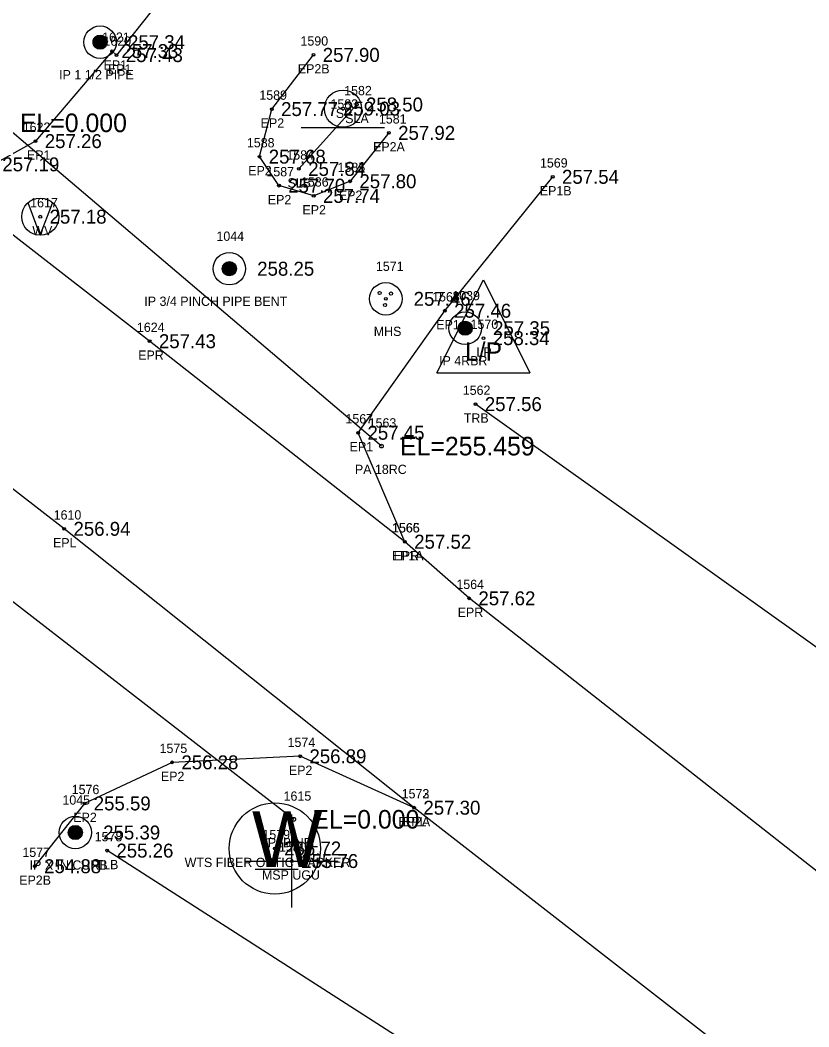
# Model space of a CAD drawing. Extents: x 1961231 to 1962574, y 799865 to 801120.
# Drawn here: x 1961462.6 to 1961547.5, y 800894.4 to 801002.7 of the extents above; entities that cross this region are included whole.
import ezdxf

# ---------------------------------------------------------------- set-up
doc = ezdxf.new("R2010")
doc.units = 0
for name, color, linetype in [('RD_EX_BldgApp', 7, 'Continuous'), ('RD_EX_BldgApp_txCode', 7, 'Continuous'), ('RD_EX_DR_Inlet', 7, 'Continuous'), ('RD_EX_DR_Pipe', 7, 'Continuous'), ('RD_EX_DR_Pipe_txCode', 7, 'Continuous'), ('RD_EX_DV_Prop_txCode', 7, 'Continuous'), ('RD_EX_DV_PropPin', 7, 'Continuous'), ('RD_EX_Misc', 7, 'Continuous'), ('RD_EX_Misc_txCode', 7, 'Continuous'), ('RD_EX_Road', 7, 'Continuous'), ('RD_EX_Road_txCode', 7, 'Continuous'), ('RD_EX_TX_BldgApp_ELEV', 7, 'Continuous'), ('RD_EX_TX_DV_Prop_ELEV', 7, 'Continuous'), ('RD_EX_TX_Misc_ELEV', 7, 'Continuous'), ('RD_EX_TX_Road_ELEV', 7, 'Continuous'), ('RD_EX_TX_UT_ELEV', 7, 'Continuous'), ('RD_EX_TX_VEG_ELEV', 7, 'Continuous'), ('RD_EX_UT', 7, 'Continuous'), ('RD_EX_UT_txCode', 7, 'Continuous'), ('RD_EX_VEG', 7, 'Continuous'), ('RD_EX_VEG_txCode', 7, 'Continuous'), ('RD_SMD_Locator', 7, 'Continuous'), ('RD_TX_Pipe_ElevEX', 7, 'Continuous')]:
    doc.layers.add(name, color=color, linetype=linetype)

msp = doc.modelspace()

# ---------------------------------------------------------------- linework, layer by layer
at = {"layer": 'RD_EX_BldgApp'}
msp.add_line((1961492.83, 800991.17), (1961501.83, 800991.17), dxfattribs=at)
msp.add_circle((1961497.35, 800993.19), 2, dxfattribs=at)
at = {"layer": 'RD_EX_DR_Inlet'}
for centre, radius in [((1961501.95, 800972.72), 1.75), ((1961501.29, 800973.35), 0.175), ((1961502.51, 800973.28), 0.175), ((1961501.87, 800972.06), 0.175)]:
    msp.add_circle(centre, radius, dxfattribs=at)
at = {"layer": 'RD_EX_DR_Pipe'}
for p, q in [((1961501.48, 800956.87), (1961460.56, 800991.66)), ((1961427.94, 800966.34), (1961492.04, 800916.71))]:
    msp.add_line(p, q, dxfattribs=at)
at = {"layer": 'RD_EX_DV_PropPin'}
for p, q in [((1961470.46, 801000.15), (1961470.46, 801000.54)), ((1961470.5, 801000.05), (1961470.5, 801000.64)), ((1961470.53, 800999.97), (1961470.53, 801000.71)), ((1961470.57, 800999.92), (1961470.57, 801000.77)), ((1961470.6, 800999.87), (1961470.6, 801000.82)), ((1961470.64, 800999.83), (1961470.64, 801000.86)), ((1961470.67, 800999.79), (1961470.67, 801000.89)), ((1961470.71, 800999.76), (1961470.71, 801000.93)), ((1961470.74, 800999.73), (1961470.74, 801000.95)), ((1961470.78, 800999.71), (1961470.78, 801000.98)), ((1961470.81, 800999.69), (1961470.81, 801001)), ((1961470.85, 800999.67), (1961470.85, 801001.02)), ((1961470.88, 800999.65), (1961470.88, 801001.04)), ((1961470.92, 800999.64), (1961470.92, 801001.05)), ((1961470.95, 800999.62), (1961470.95, 801001.06)), ((1961470.99, 800999.61), (1961470.99, 801001.07)), ((1961471.02, 800999.6), (1961471.02, 801001.08)), ((1961471.06, 800999.6), (1961471.06, 801001.09)), ((1961471.09, 800999.59), (1961471.09, 801001.1)), ((1961471.13, 800999.59), (1961471.13, 801001.1)), ((1961471.16, 800999.58), (1961471.16, 801001.1)), ((1961471.2, 800999.58), (1961471.2, 801001.1)), ((1961471.23, 800999.58), (1961471.23, 801001.1)), ((1961471.27, 800999.59), (1961471.27, 801001.1)), ((1961471.3, 800999.59), (1961471.3, 801001.1)), ((1961471.34, 800999.6), (1961471.34, 801001.09)), ((1961471.37, 800999.6), (1961471.37, 801001.08)), ((1961471.41, 800999.61), (1961471.41, 801001.07)), ((1961471.44, 800999.62), (1961471.44, 801001.06)), ((1961471.48, 800999.64), (1961471.48, 801001.05)), ((1961471.51, 800999.65), (1961471.51, 801001.04)), ((1961471.55, 800999.67), (1961471.55, 801001.02)), ((1961471.58, 800999.69), (1961471.58, 801001)), ((1961471.62, 800999.71), (1961471.62, 801000.98)), ((1961471.65, 800999.73), (1961471.65, 801000.95)), ((1961471.69, 800999.76), (1961471.69, 801000.93)), ((1961471.72, 800999.79), (1961471.72, 801000.89)), ((1961471.76, 800999.83), (1961471.76, 801000.86)), ((1961471.79, 800999.87), (1961471.79, 801000.82)), ((1961471.83, 800999.92), (1961471.83, 801000.77)), ((1961471.86, 800999.97), (1961471.86, 801000.71)), ((1961471.9, 801000.05), (1961471.9, 801000.64)), ((1961471.93, 801000.15), (1961471.93, 801000.54)), ((1961484.44, 800975.59), (1961484.44, 800976.33)), ((1961484.48, 800975.53), (1961484.48, 800976.39)), ((1961484.51, 800975.49), (1961484.51, 800976.43)), ((1961484.55, 800975.45), (1961484.55, 800976.48)), ((1961484.58, 800975.41), (1961484.58, 800976.51)), ((1961484.62, 800975.38), (1961484.62, 800976.54)), ((1961484.65, 800975.35), (1961484.65, 800976.57)), ((1961484.69, 800975.33), (1961484.69, 800976.59)), ((1961484.72, 800975.3), (1961484.72, 800976.62)), ((1961484.76, 800975.28), (1961484.76, 800976.64)), ((1961484.79, 800975.27), (1961484.79, 800976.65)), ((1961484.83, 800975.25), (1961484.83, 800976.67)), ((1961484.86, 800975.24), (1961484.86, 800976.68)), ((1961484.9, 800975.23), (1961484.9, 800976.69)), ((1961484.93, 800975.22), (1961484.93, 800976.7)), ((1961484.97, 800975.21), (1961484.97, 800976.71)), ((1961485, 800975.21), (1961485, 800976.71)), ((1961485.04, 800975.2), (1961485.04, 800976.72)), ((1961485.07, 800975.2), (1961485.07, 800976.72)), ((1961485.11, 800975.2), (1961485.11, 800976.72)), ((1961485.14, 800975.2), (1961485.14, 800976.72)), ((1961485.18, 800975.2), (1961485.18, 800976.72)), ((1961485.21, 800975.21), (1961485.21, 800976.71)), ((1961485.25, 800975.21), (1961485.25, 800976.71)), ((1961485.28, 800975.22), (1961485.28, 800976.7)), ((1961485.32, 800975.23), (1961485.32, 800976.69)), ((1961485.35, 800975.24), (1961485.35, 800976.68)), ((1961485.39, 800975.25), (1961485.39, 800976.67)), ((1961485.42, 800975.27), (1961485.42, 800976.65)), ((1961485.46, 800975.28), (1961485.46, 800976.64)), ((1961485.49, 800975.3), (1961485.49, 800976.62)), ((1961485.53, 800975.33), (1961485.53, 800976.59)), ((1961485.56, 800975.35), (1961485.56, 800976.57)), ((1961485.6, 800975.38), (1961485.6, 800976.54)), ((1961485.63, 800975.41), (1961485.63, 800976.51)), ((1961485.67, 800975.45), (1961485.67, 800976.48)), ((1961485.7, 800975.49), (1961485.7, 800976.43)), ((1961485.74, 800975.53), (1961485.74, 800976.39)), ((1961485.77, 800975.59), (1961485.77, 800976.33)), ((1961484.37, 800975.76), (1961484.37, 800976.16)), ((1961484.41, 800975.66), (1961484.41, 800976.26)), ((1961485.81, 800975.66), (1961485.81, 800976.26)), ((1961485.84, 800975.76), (1961485.84, 800976.16)), ((1961509.8, 800969.26), (1961509.8, 800969.86)), ((1961509.83, 800969.19), (1961509.83, 800969.93)), ((1961509.87, 800969.14), (1961509.87, 800969.99)), ((1961509.9, 800969.09), (1961509.9, 800970.04)), ((1961509.94, 800969.05), (1961509.94, 800970.08)), ((1961509.97, 800969.01), (1961509.97, 800970.11)), ((1961510.01, 800968.98), (1961510.01, 800970.14)), ((1961510.04, 800968.95), (1961510.04, 800970.17)), ((1961510.08, 800968.93), (1961510.08, 800970.2)), ((1961510.11, 800968.91), (1961510.11, 800970.22)), ((1961510.15, 800968.89), (1961510.15, 800970.24)), ((1961510.18, 800968.87), (1961510.18, 800970.25)), ((1961510.22, 800968.85), (1961510.22, 800970.27)), ((1961510.25, 800968.84), (1961510.25, 800970.28)), ((1961510.29, 800968.83), (1961510.29, 800970.29)), ((1961510.32, 800968.82), (1961510.32, 800970.3)), ((1961510.36, 800968.81), (1961510.36, 800970.31)), ((1961510.39, 800968.81), (1961510.39, 800970.32)), ((1961510.43, 800968.8), (1961510.43, 800970.32)), ((1961510.46, 800968.8), (1961510.46, 800970.32)), ((1961510.5, 800968.8), (1961510.5, 800970.32)), ((1961510.53, 800968.8), (1961510.53, 800970.32)), ((1961510.57, 800968.8), (1961510.57, 800970.32)), ((1961510.6, 800968.81), (1961510.6, 800970.32)), ((1961510.64, 800968.81), (1961510.64, 800970.31)), ((1961510.67, 800968.82), (1961510.67, 800970.3)), ((1961510.71, 800968.83), (1961510.71, 800970.29)), ((1961510.74, 800968.84), (1961510.74, 800970.28)), ((1961510.78, 800968.85), (1961510.78, 800970.27)), ((1961510.81, 800968.87), (1961510.81, 800970.25)), ((1961510.85, 800968.89), (1961510.85, 800970.24)), ((1961510.88, 800968.91), (1961510.88, 800970.22)), ((1961510.92, 800968.93), (1961510.92, 800970.2)), ((1961510.95, 800968.95), (1961510.95, 800970.17)), ((1961510.99, 800968.98), (1961510.99, 800970.14)), ((1961511.02, 800969.01), (1961511.02, 800970.11)), ((1961511.06, 800969.05), (1961511.06, 800970.08)), ((1961511.09, 800969.09), (1961511.09, 800970.04)), ((1961511.13, 800969.14), (1961511.13, 800969.99)), ((1961511.16, 800969.19), (1961511.16, 800969.93)), ((1961511.2, 800969.26), (1961511.2, 800969.86)), ((1961509.76, 800969.37), (1961509.76, 800969.76)), ((1961511.23, 800969.37), (1961511.23, 800969.76)), ((1961467.86, 800914.92), (1961467.86, 800915.66)), ((1961467.9, 800914.86), (1961467.9, 800915.71)), ((1961467.93, 800914.81), (1961467.93, 800915.76)), ((1961467.97, 800914.77), (1961467.97, 800915.8)), ((1961468, 800914.74), (1961468, 800915.84)), ((1961468.04, 800914.71), (1961468.04, 800915.87)), ((1961468.07, 800914.68), (1961468.07, 800915.9)), ((1961468.11, 800914.65), (1961468.11, 800915.92)), ((1961468.14, 800914.63), (1961468.14, 800915.94)), ((1961468.18, 800914.61), (1961468.18, 800915.96)), ((1961468.21, 800914.59), (1961468.21, 800915.98)), ((1961468.25, 800914.58), (1961468.25, 800916)), ((1961468.28, 800914.57), (1961468.28, 800916.01)), ((1961468.32, 800914.56), (1961468.32, 800916.02)), ((1961468.35, 800914.55), (1961468.35, 800916.03)), ((1961468.39, 800914.54), (1961468.39, 800916.04)), ((1961468.42, 800914.53), (1961468.42, 800916.04)), ((1961468.46, 800914.53), (1961468.46, 800916.05)), ((1961468.49, 800914.53), (1961468.49, 800916.05)), ((1961468.53, 800914.53), (1961468.53, 800916.05)), ((1961468.56, 800914.53), (1961468.56, 800916.05)), ((1961468.6, 800914.53), (1961468.6, 800916.05)), ((1961468.63, 800914.53), (1961468.63, 800916.04)), ((1961468.67, 800914.54), (1961468.67, 800916.04)), ((1961468.7, 800914.55), (1961468.7, 800916.03)), ((1961468.74, 800914.56), (1961468.74, 800916.02)), ((1961468.77, 800914.57), (1961468.77, 800916.01)), ((1961468.81, 800914.58), (1961468.81, 800916)), ((1961468.84, 800914.59), (1961468.84, 800915.98)), ((1961468.88, 800914.61), (1961468.88, 800915.96)), ((1961468.91, 800914.63), (1961468.91, 800915.94)), ((1961468.95, 800914.65), (1961468.95, 800915.92)), ((1961468.98, 800914.68), (1961468.98, 800915.9)), ((1961469.02, 800914.71), (1961469.02, 800915.87)), ((1961469.05, 800914.74), (1961469.05, 800915.84)), ((1961469.09, 800914.77), (1961469.09, 800915.8)), ((1961469.12, 800914.81), (1961469.12, 800915.76)), ((1961469.16, 800914.86), (1961469.16, 800915.71)), ((1961469.19, 800914.92), (1961469.19, 800915.66)), ((1961467.79, 800915.09), (1961467.79, 800915.48)), ((1961467.83, 800914.99), (1961467.83, 800915.59)), ((1961469.23, 800914.99), (1961469.23, 800915.59)), ((1961469.26, 800915.09), (1961469.26, 800915.48))]:
    msp.add_line(p, q, dxfattribs=at)
for centre, radius in [((1961471.2, 801000.34), 1.75), ((1961471.2, 801000.34), 0.761), ((1961485.11, 800975.96), 1.75), ((1961485.11, 800975.96), 0.761), ((1961510.5, 800969.56), 1.75), ((1961510.5, 800969.56), 0.761), ((1961468.53, 800915.29), 1.75), ((1961468.53, 800915.29), 0.761)]:
    msp.add_circle(centre, radius, dxfattribs=at)
at = {"layer": 'RD_EX_Misc'}
for p, q in [((1961491.84, 800907.22), (1961491.84, 800917.22)), ((1961486.84, 800912.22), (1961496.84, 800912.22))]:
    msp.add_line(p, q, dxfattribs=at)
at = {"layer": 'RD_EX_Road'}
for points in [[(1961735.63, 800762.82), (1961702.92, 800788.52), (1961676.16, 800810.27), (1961651.45, 800830.73), (1961641.14, 800839.02), (1961595.18, 800874.45), (1961552.9, 800907.54), (1961510.92, 800940.49), (1961504.01, 800946.58), (1961476.53, 800968.16), (1961444.88, 800992.72), (1961406.41, 801021.23), (1961370.69, 801045.26)], [(1961722.95, 800745.11), (1961689.13, 800771.93), (1961670.14, 800787.03), (1961660.52, 800795.31), (1961637.49, 800813.67), (1961617.86, 800829), (1961581.48, 800857.91), (1961538.42, 800891.96), (1961505, 800917.96), (1961467.33, 800947.97), (1961432.02, 800975.33), (1961392.71, 801004.33), (1961360.06, 801026.78)], [(1961484.46, 801013.43), (1961472.97, 800998.95), (1961472.49, 800999.38), (1961464.24, 800989.69), (1961459.67, 800987.19), (1961451.78, 800987.58)], [(1961502.28, 800990.58), (1961498.11, 800985.37), (1961494.19, 800983.8), (1961490.45, 800984.9), (1961488.35, 800988.02), (1961489.68, 800993.14), (1961494.16, 800998.97)], [(1961504.01, 800946.58), (1961498.98, 800958.31), (1961508.31, 800971.44), (1961519.92, 800985.85)], [(1961505, 800917.96), (1961492.73, 800923.49), (1961478.95, 800922.84), (1961469.51, 800918.42), (1961464.17, 800911.66)]]:
    msp.add_lwpolyline(points, dxfattribs=at)
at = {"layer": 'RD_EX_UT'}
for p, q in [((1961464.76, 800979.57), (1961463.45, 800983.05)), ((1961464.76, 800979.57), (1961466.08, 800983.01)), ((1961507.46, 800964.77), (1961512.46, 800974.77)), ((1961512.46, 800974.77), (1961517.46, 800964.77)), ((1961507.46, 800964.77), (1961517.46, 800964.77)), ((1961487.88, 800911.36), (1961492.51, 800911.36))]:
    msp.add_line(p, q, dxfattribs=at)
for centre, radius in [((1961464.76, 800981.56), 2), ((1961490.01, 800913.57), 4.91)]:
    msp.add_circle(centre, radius, dxfattribs=at)
at = {"layer": 'RD_EX_VEG'}
msp.add_line((1961498.82, 800993.63), (1961492.6, 800986.7), dxfattribs=at)
for points in [[(1961789.73, 800785.49), (1961758.16, 800795.77), (1961726.49, 800818.25), (1961689.15, 800828.3), (1961645.31, 800860.5), (1961608.13, 800895.26), (1961564.66, 800923.57), (1961511.61, 800961.39)], [(1961584.58, 800795.58), (1961602.69, 800819.62), (1961568.89, 800845.14), (1961527.21, 800877.9), (1961471.95, 800913.34)]]:
    msp.add_lwpolyline(points, dxfattribs=at)
at = {"layer": 'RD_SMD_Locator'}
for centre, radius in [((1961471.2, 801000.34), 0.15), ((1961472.49, 800999.38), 0.15), ((1961472.97, 800998.95), 0.15), ((1961494.16, 800998.97), 0.15), ((1961498.82, 800993.63), 0.15), ((1961489.68, 800993.14), 0.15), ((1961497.35, 800993.19), 0.15), ((1961502.28, 800990.58), 0.15), ((1961464.24, 800989.69), 0.15), ((1961488.35, 800988.02), 0.15), ((1961492.6, 800986.7), 0.15), ((1961490.45, 800984.9), 0.15), ((1961498.11, 800985.37), 0.15), ((1961519.92, 800985.85), 0.15), ((1961494.19, 800983.8), 0.15), ((1961464.76, 800981.56), 0.15), ((1961485.11, 800975.96), 0.15), ((1961501.95, 800972.72), 0.15), ((1961508.31, 800971.44), 0.15), ((1961510.5, 800969.56), 0.15), ((1961476.53, 800968.16), 0.15), ((1961512.46, 800968.49), 0.15), ((1961511.61, 800961.39), 0.15), ((1961498.98, 800958.31), 0.15), ((1961501.48, 800956.87), 0.2), ((1961467.33, 800947.97), 0.15), ((1961504.01, 800946.58), 0.15), ((1961504.01, 800946.58), 0.15), ((1961510.92, 800940.49), 0.15), ((1961492.73, 800923.49), 0.15), ((1961478.95, 800922.84), 0.15), ((1961469.51, 800918.42), 0.15), ((1961505, 800917.96), 0.15), ((1961505, 800917.96), 0.15), ((1961492.04, 800916.71), 0.2), ((1961468.53, 800915.29), 0.15), ((1961471.95, 800913.34), 0.15), ((1961490.01, 800913.57), 0.15), ((1961464.17, 800911.66), 0.15), ((1961491.84, 800912.22), 0.15)]:
    msp.add_circle(centre, radius, dxfattribs=at)

# ---------------------------------------------------------------- texts
at = {"layer": 'RD_EX_BldgApp_txCode'}
for s, p in [('1583', (1961496, 800993.19)), ('SP', (1961496.57, 800992.19))]:
    msp.add_text(s, height=1, dxfattribs=at).set_placement(p)
at = {"layer": 'RD_EX_DR_Pipe_txCode'}
for s, p in [('1563', (1961500.11, 800958.87)), ('PA 18RC', (1961498.63, 800953.87)), ('1615', (1961490.95, 800918.71)), ('P1B NFL', (1961489.25, 800913.71))]:
    msp.add_text(s, height=1, dxfattribs=at).set_placement(p)
at = {"layer": 'RD_EX_DV_Prop_txCode'}
for s, p in [('IP 1 1/2 PIPE', (1961466.79, 800996.34)), ('1044', (1961483.72, 800978.96)), ('1039', (1961509.11, 800972.56)), ('IP 3/4 PINCH PIPE BENT', (1961475.96, 800971.96)), ('IP 4RBR', (1961507.69, 800965.56)), ('1045', (1961467.14, 800918.29)), ('IP X IN CURB', (1961463.61, 800911.29))]:
    msp.add_text(s, height=1, dxfattribs=at).set_placement(p)
at = {"layer": 'RD_EX_Misc_txCode'}
for s, p in [('1580', (1961490.45, 800913.22)), ('MSP UGU', (1961488.62, 800910.22))]:
    msp.add_text(s, height=1, dxfattribs=at).set_placement(p)
at = {"layer": 'RD_EX_Road_txCode'}
for s, p in [('1621', (1961471.41, 801000.38)), ('1620', (1961471.56, 800999.95)), ('1590', (1961492.77, 800999.97)), ('EP1', (1961471.57, 800997.38)), ('EP2B', (1961492.48, 800996.97)), ('EP1', (1961472.05, 800996.95)), ('1589', (1961488.34, 800994.14)), ('1581', (1961501.21, 800991.58)), ('1622', (1961462.87, 800990.69)), ('EP2', (1961488.48, 800991.14)), ('1588', (1961487, 800989.02)), ('EP2A', (1961500.58, 800988.58)), ('EP1', (1961463.32, 800987.69)), ('1585', (1961496.76, 800986.37)), ('1569', (1961518.55, 800986.85)), ('EP2', (1961487.14, 800986.02)), ('1587', (1961489.1, 800985.9)), ('1586', (1961492.82, 800984.8)), ('EP2', (1961489.25, 800982.9)), ('EP2', (1961496.9, 800983.37)), ('EP1B', (1961518.53, 800983.85)), ('EP2', (1961492.98, 800981.8)), ('1568', (1961506.94, 800972.44)), ('1624', (1961475.16, 800969.16)), ('EP1', (1961507.39, 800969.44)), ('EPR', (1961475.3, 800966.16)), ('1567', (1961497.61, 800959.31)), ('EP1', (1961498.06, 800956.31)), ('1610', (1961466.2, 800948.97)), ('1566', (1961502.61, 800947.58)), ('1565', (1961502.64, 800947.58)), ('EPL', (1961466.13, 800945.97)), ('EP1A', (1961502.6, 800944.58)), ('EPR', (1961502.78, 800944.58)), ('1564', (1961509.55, 800941.49)), ('EPR', (1961509.69, 800938.49)), ('1574', (1961491.38, 800924.49)), ('1575', (1961477.6, 800923.84)), ('EP2', (1961491.52, 800921.49)), ('EP2', (1961477.74, 800920.84)), ('1576', (1961468.14, 800919.42)), ('1572', (1961503.66, 800918.96)), ('1573', (1961503.66, 800918.96)), ('EP2', (1961468.31, 800916.42)), ('EP2A', (1961503.31, 800915.96)), ('EPL', (1961503.8, 800915.96)), ('1577', (1961462.83, 800912.66)), ('EP2B', (1961462.49, 800909.66))]:
    msp.add_text(s, height=1, dxfattribs=at).set_placement(p)
at = {"layer": 'RD_EX_TX_BldgApp_ELEV'}
msp.add_text('259.03', height=1.5, dxfattribs=at).set_placement((1961497.35, 800992.44))
at = {"layer": 'RD_EX_TX_DV_Prop_ELEV'}
for s, p in [('257.34', (1961474.2, 800999.59)), ('258.25', (1961488.11, 800975.21)), ('257.35', (1961513.5, 800968.81)), ('255.39', (1961471.53, 800914.54))]:
    msp.add_text(s, height=1.5, dxfattribs=at).set_placement(p)
at = {"layer": 'RD_EX_TX_Misc_ELEV'}
msp.add_text('255.76', height=1.5, dxfattribs=at).set_placement((1961492.84, 800911.47))
at = {"layer": 'RD_EX_TX_Road_ELEV'}
for s, p in [('257.33', (1961473.49, 800998.63)), ('257.43', (1961473.97, 800998.2)), ('257.90', (1961495.16, 800998.22)), ('257.77', (1961490.68, 800992.39)), ('257.26', (1961465.24, 800988.94)), ('257.92', (1961503.28, 800989.83)), ('257.68', (1961489.35, 800987.27)), ('257.19', (1961460.67, 800986.44)), ('257.80', (1961499.11, 800984.62)), ('257.54', (1961520.92, 800985.1)), ('257.70', (1961491.45, 800984.15)), ('257.74', (1961495.19, 800983.05)), ('257.46', (1961509.31, 800970.69)), ('257.43', (1961477.53, 800967.41)), ('257.45', (1961499.98, 800957.56)), ('256.94', (1961468.33, 800947.22)), ('257.52', (1961505.01, 800945.83)), ('257.52', (1961505.01, 800945.83)), ('257.62', (1961511.92, 800939.74)), ('256.28', (1961479.95, 800922.09)), ('256.89', (1961493.73, 800922.74)), ('255.59', (1961470.51, 800917.67)), ('257.30', (1961506, 800917.21)), ('257.30', (1961506, 800917.21)), ('254.88', (1961465.17, 800910.91))]:
    msp.add_text(s, height=1.5, dxfattribs=at).set_placement(p)
at = {"layer": 'RD_EX_TX_UT_ELEV'}
for s, p in [('257.18', (1961465.76, 800980.81)), ('257.46', (1961504.95, 800971.97)), ('258.34', (1961513.46, 800967.74)), ('255.72', (1961491.01, 800912.82))]:
    msp.add_text(s, height=1.5, dxfattribs=at).set_placement(p)
at = {"layer": 'RD_EX_TX_VEG_ELEV'}
for s, p in [('258.50', (1961499.82, 800992.88)), ('257.84', (1961493.6, 800985.95)), ('257.56', (1961512.61, 800960.64)), ('255.26', (1961472.95, 800912.59))]:
    msp.add_text(s, height=1.5, dxfattribs=at).set_placement(p)
at = {"layer": 'RD_EX_UT'}
for s, height, p in [('L/P', 2, (1961510.46, 800966.05)), ('W', 6, (1961487.55, 800911.57))]:
    msp.add_text(s, height=height, dxfattribs=at).set_placement(p)
at = {"layer": 'RD_EX_UT_txCode'}
for s, p in [('1617', (1961463.67, 800982.56)), ('WV', (1961463.9, 800979.56)), ('1571', (1961500.89, 800975.72)), ('1570', (1961511.08, 800969.49)), ('MHS', (1961500.66, 800968.72)), ('LP', (1961511.71, 800966.49)), ('1579', (1961488.67, 800914.57)), ('WTS FIBER OPTIC MARKER', (1961480.3, 800911.57))]:
    msp.add_text(s, height=1, dxfattribs=at).set_placement(p)
at = {"layer": 'RD_EX_VEG_txCode'}
for s, p in [('1582', (1961497.47, 800994.63)), ('SLA', (1961497.58, 800991.63)), ('1584', (1961491.25, 800987.7)), ('SLB', (1961491.37, 800984.7)), ('1562', (1961510.24, 800962.39)), ('TRB', (1961510.35, 800959.39)), ('1578', (1961470.61, 800914.34)), ('TLB', (1961470.71, 800911.34))]:
    msp.add_text(s, height=1, dxfattribs=at).set_placement(p)
at = {"layer": 'RD_TX_Pipe_ElevEX'}
for s, p in [('EL=0.000', (1961462.56, 800990.66)), ('EL=255.459', (1961503.48, 800955.87)), ('EL=0.000', (1961494.04, 800915.71))]:
    msp.add_text(s, height=2, dxfattribs=at).set_placement(p)

doc.saveas('drawing.dxf')
